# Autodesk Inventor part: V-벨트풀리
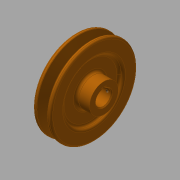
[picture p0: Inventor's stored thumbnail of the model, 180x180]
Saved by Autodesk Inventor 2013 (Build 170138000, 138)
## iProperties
Created: 2015-09
Part Number: V-벨트풀리
Material: 강철, 연강
Document SubType Name: Modeling
Designer: mduedu
Density: 7.86 g/cm^3
Mass: 779.014 g
Surface Area: 277.465 cm^2
Volume: 99.1112 cm^3
Author: mduedu
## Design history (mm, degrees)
sketch "스케치1"
  geometry: L1 (-10, 0)-(10, 0); L2 (-10, 0)-(-10, 48); L3 (-10, 48)-(-5.976, 48); L4 (-5.976, 48)-(-2.154, 35.5); L5 (-2.154, 35.5)-(2.154, 35.5); L6 (2.154, 35.5)-(5.976, 48); L7 (5.976, 48)-(10, 48); L8 (10, 48)-(10, 0); L9 (0, 0)-(0, 35.5); L10 (-10, 43.5)-(10, 43.5); 3 further points
  constraints: 20 end point, 6 point on line, 3 perpendicular, 2 midpoint, 2 parallel, 2 symmetric about line, 1 coincident, 1 collinear, 1 equal length, 1 horizontal, 1 vertical, 1 vertical alignment
  dimensions: "d0" = 20 distance between parallel lines of L8 L2; "d2" = 96 diameter of L3 L1; "d3" = 87 diameter of L10 L1; "d4" = 4.5 distance between parallel lines of L10 L3 (derived); "d5" = 8 distance between parallel lines of L5 L10; "d6" = 9.2 distance of point (4.6, 43.5) point (-4.6, 43.5); "d7" = 34 deg angle of L6 L4
revolve "회전1" sketch "스케치1" stored, may be unused: angle "d8" = 90 deg
sketch "스케치2"
  geometry: C1 r 16 at (0, 0); 1 further point
  constraints: 1 centre point, 1 coincident
  dimensions: "d9" = 32 diameter of C1
extrude "돌출1" join sketch "스케치2" distance "d10" = 11; taper "d11" = 0 deg
fillet "모깎기1" dims "d12" = 1, "d13" = 0.5, "d14" = 2
sketch "스케치3"
  geometry: C1 r 16 at (0, 0) reference; C2 r 32 at (0, 0); 1 further point
  constraints: 1 centre point, 1 coincident
  dimensions: "d15" = 64 diameter of C2
extrude "돌출2" cut sketch "스케치3" distance "d16" = 4; taper "d17" = 0 deg
fillet "모깎기2" dims "d18" = 3
fillet "모깎기3" dims "d19" = 3
fillet "모깎기4" dims "d20" = 3
sketch "스케치4"
  geometry: C1 r 8.5 at (0, 0); 1 further point
  constraints: 1 centre point, 1 coincident
  dimensions: "d21" = 17 diameter of C1
extrude "돌출3" cut sketch "스케치4" stored distance "d22" = 4; taper "d23" = 0 deg
sketch "스케치5"
  geometry: L1 (-2.5, 8.124)-(2.5, 8.124); L2 (2.5, 8.124)-(2.5, 10.8); L3 (2.5, 10.8)-(-2.5, 10.8); L4 (-2.5, 10.8)-(-2.5, 8.124); A1 r 8.5 centre (0, 0) between (-2.5, 8.124) and (2.5, 8.124) reference; 2 further points
  constraints: 8 end point, 3 point on circle, 2 parallel, 1 horizontal, 1 perpendicular, 1 vertical alignment
  dimensions: "d24" = 5 distance of L2.end L3.end; "d26" = 19.3 distance from line of L3 point (0, -8.5)
extrude "돌출4" cut sketch "스케치5" stored distance "d27" = 4; taper "d28" = 0 deg
chamfer "모따기1" distance "d29" = 1; stored, may be unused: second distance "d30" = 2, angle "d31" = 45 deg
node "작업 평면1"
sketch "스케치6"
  geometry: L1 (-11, 16)-(-11, -16) reference; 2 further points
  constraints: 1 horizontal alignment
  dimensions: "d32" = 5 distance from line of point (-6, 0) L1
hole "구멍1" sketch "스케치6" at (-6, 0) diameter "d33" = 3.242; stored, may be unused: countersink angle "d37" = 90 deg, drill point angle "d39" = 118 deg; dims "d34" = 6, "d35" = 4, "d36" = 2, "d38" = 8
node "솔리드1"
mirror "대칭1"
